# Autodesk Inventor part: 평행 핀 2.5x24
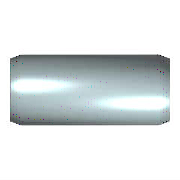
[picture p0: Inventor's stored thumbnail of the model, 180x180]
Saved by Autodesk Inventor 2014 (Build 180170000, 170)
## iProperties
IsCustomPart: 1
Created: 2012-02
Part Number: 평행 핀 2.5x24
Material: 강철, 연강
Description: 평행 핀
Document SubType Name: Modeling
Standard: KS B 1320
Designer: mduedu
Standards Organization: KS
Language: ko-KR
Size Designation: B 2.5 x  24
Categories: <MemberInstance><Categories><Category DisplayName="조임쇠" InternalName="e4da775c-781d-43d5-af7c-5136215cf5a6" Mnemonic="FSTN"><Category DisplayName="핀" InternalNa
Density: 1 g/cm^3
Appearance: 노란색
Author: mduedu
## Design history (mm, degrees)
sketch "스케치"
  geometry: C1 r 1.25 at (0, 0); 1 further point
  constraints: 1 centre point, 1 coincident
  dimensions: "d1" = 2.5 diameter of C1 (= NND)
extrude "본체" new body sketch "스케치" distance "d2" = 24 (= NLG); taper "d3" = 0 deg
chamfer "스케치2" distance "d8" = 0.4 (= PHH); stored, may be unused: angle "d9" = 15 deg (= FAWI), second distance "d12" = 0.4 (= PHH)
node "작업 평면1"
body "Solid1"
chamfer "모따기1" distance "d4" = 0.4 (= PHH); stored, may be unused: angle "d5" = 15 deg (= FAWI), second distance "d11" = 0.4 (= PHH)
other parameters: "NND" = 2.5 [user parameter; used in 1 equation term], "NLG" = 24 [user parameter; used in 1 equation term], "PHH" = 0.4 [user parameter; used in 4 equation terms], "FAWI" = 15 deg [user parameter; used in 2 equation terms], "d13" = 0, "d15" = 0, "d16" = 0, "KAH" = 0.3 [user parameter]
